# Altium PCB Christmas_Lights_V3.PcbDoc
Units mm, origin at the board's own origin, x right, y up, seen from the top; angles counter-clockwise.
Board outline 88.09 x 97.97 mm, 4 copper layers (Top Layer, Layer 1, Layer 2, Bottom Layer), stack 1.547 mm thick; 70 components, 43 nets, 269 pads, 454 vias.
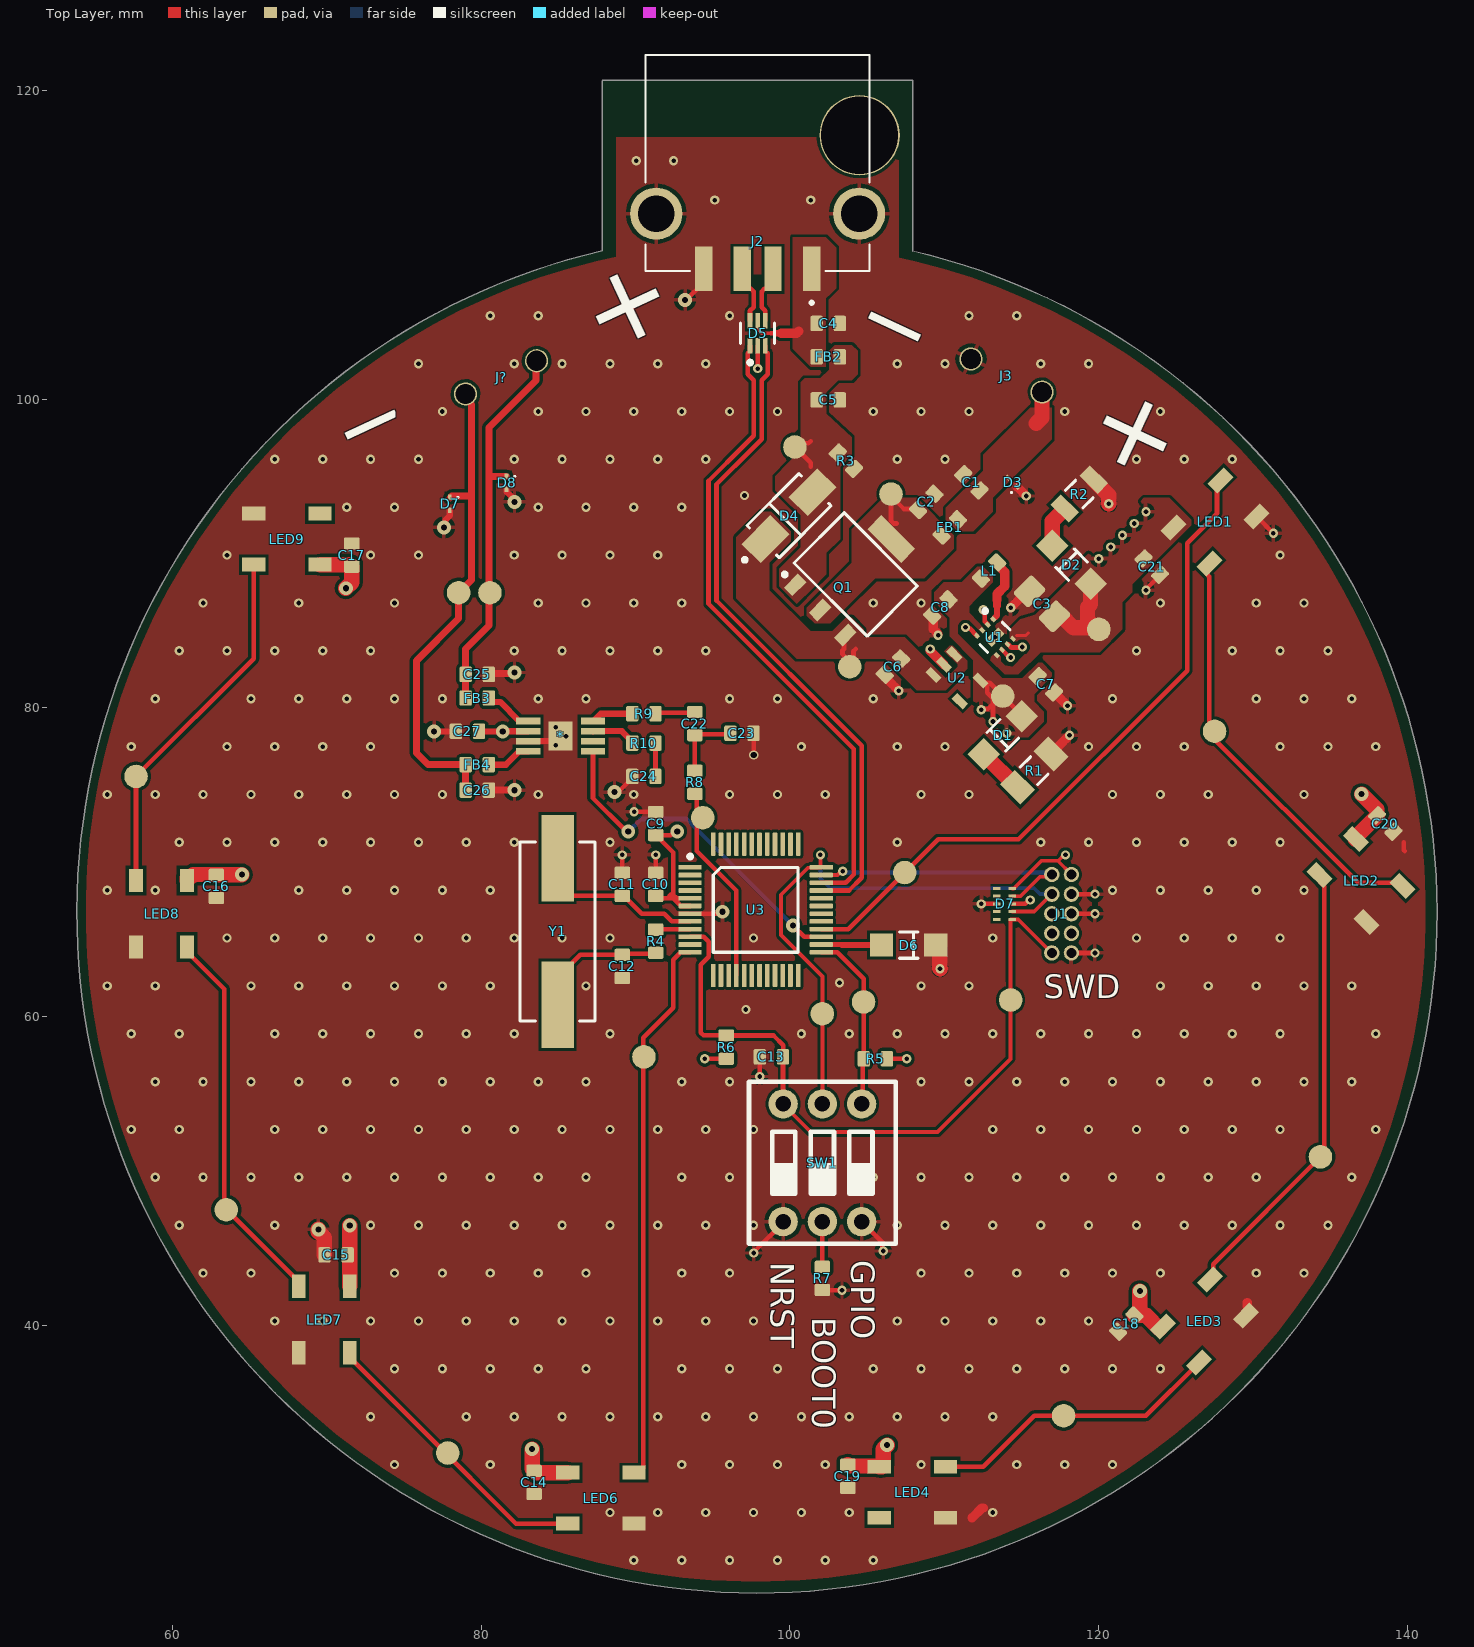
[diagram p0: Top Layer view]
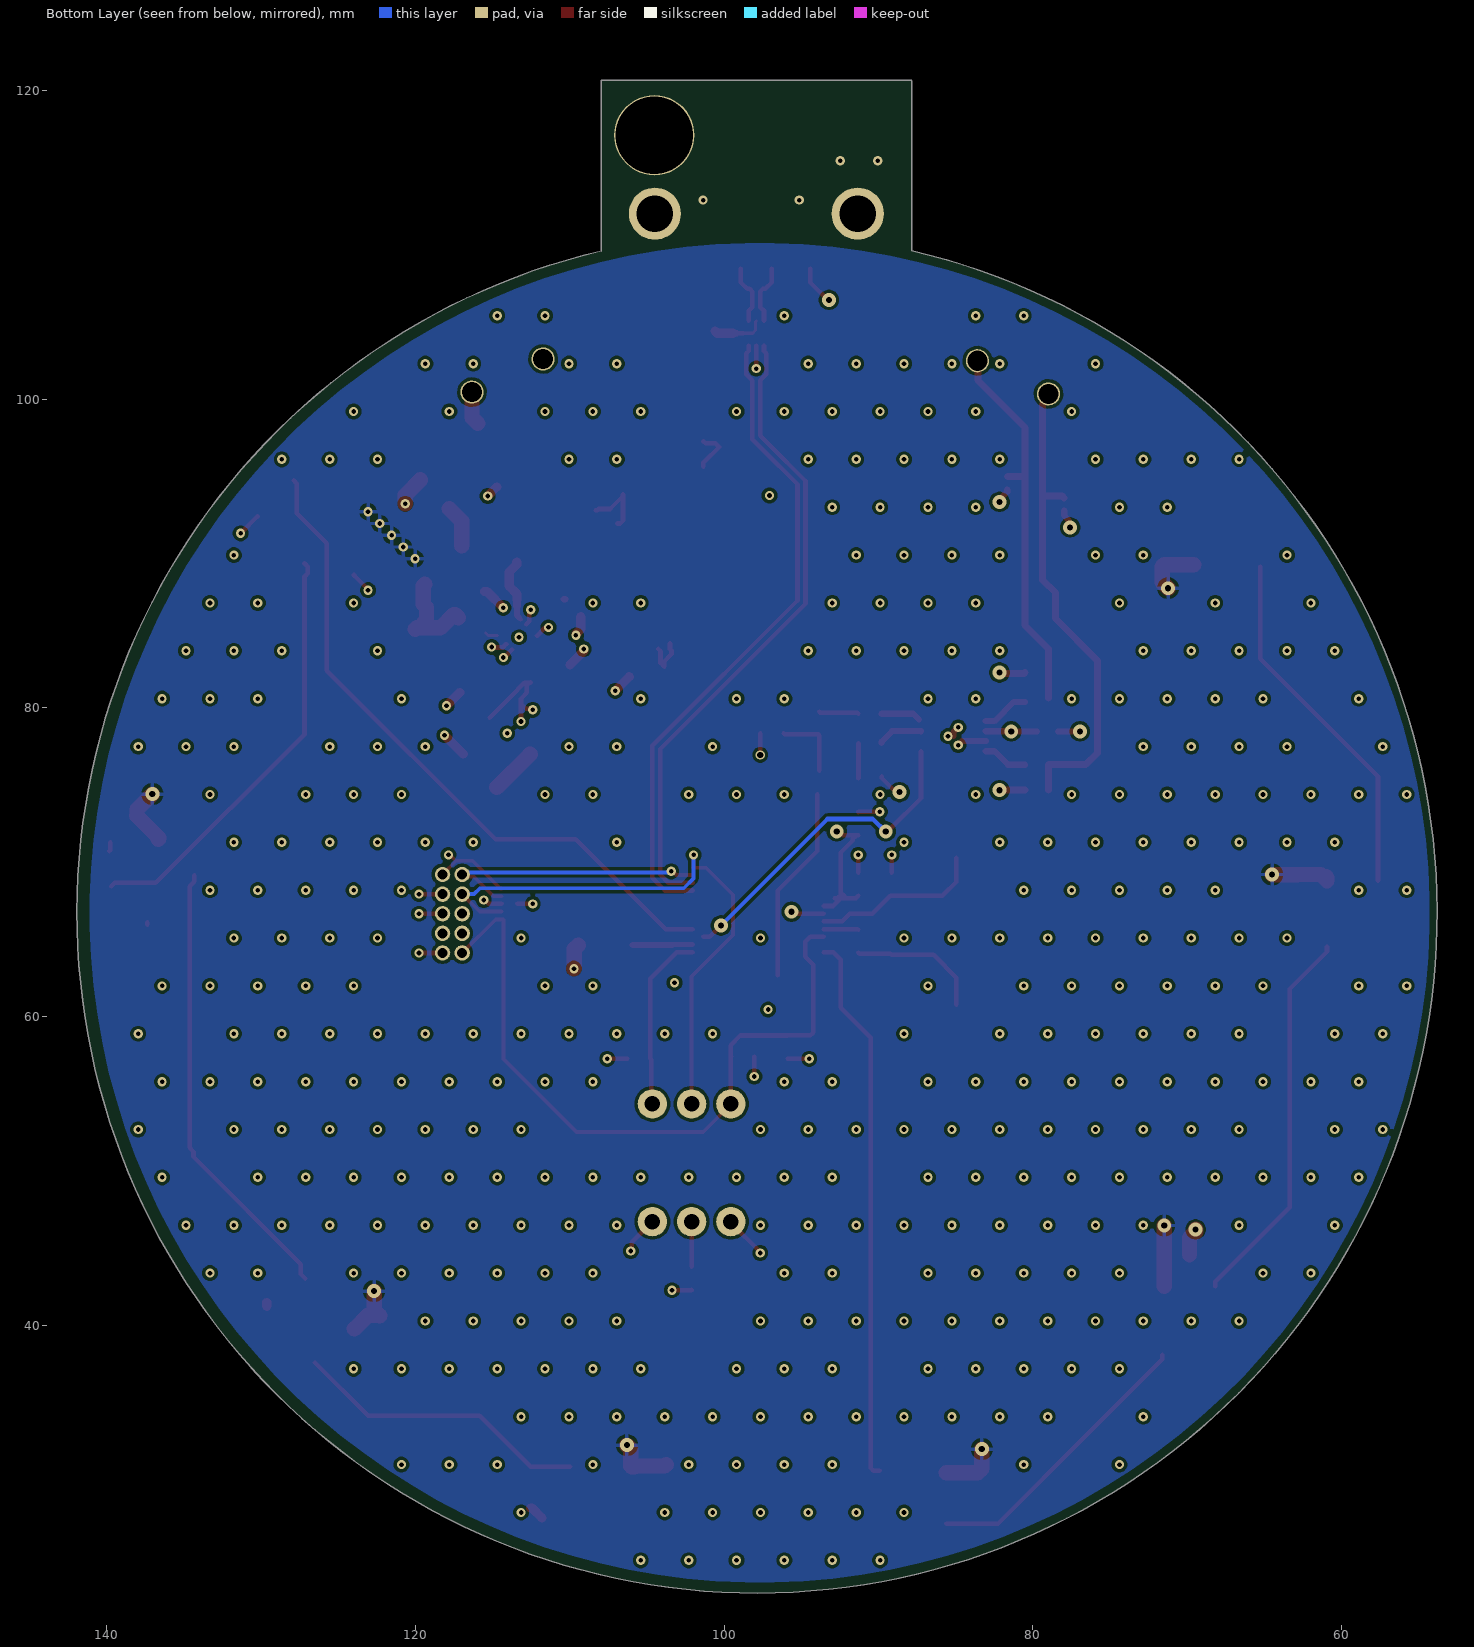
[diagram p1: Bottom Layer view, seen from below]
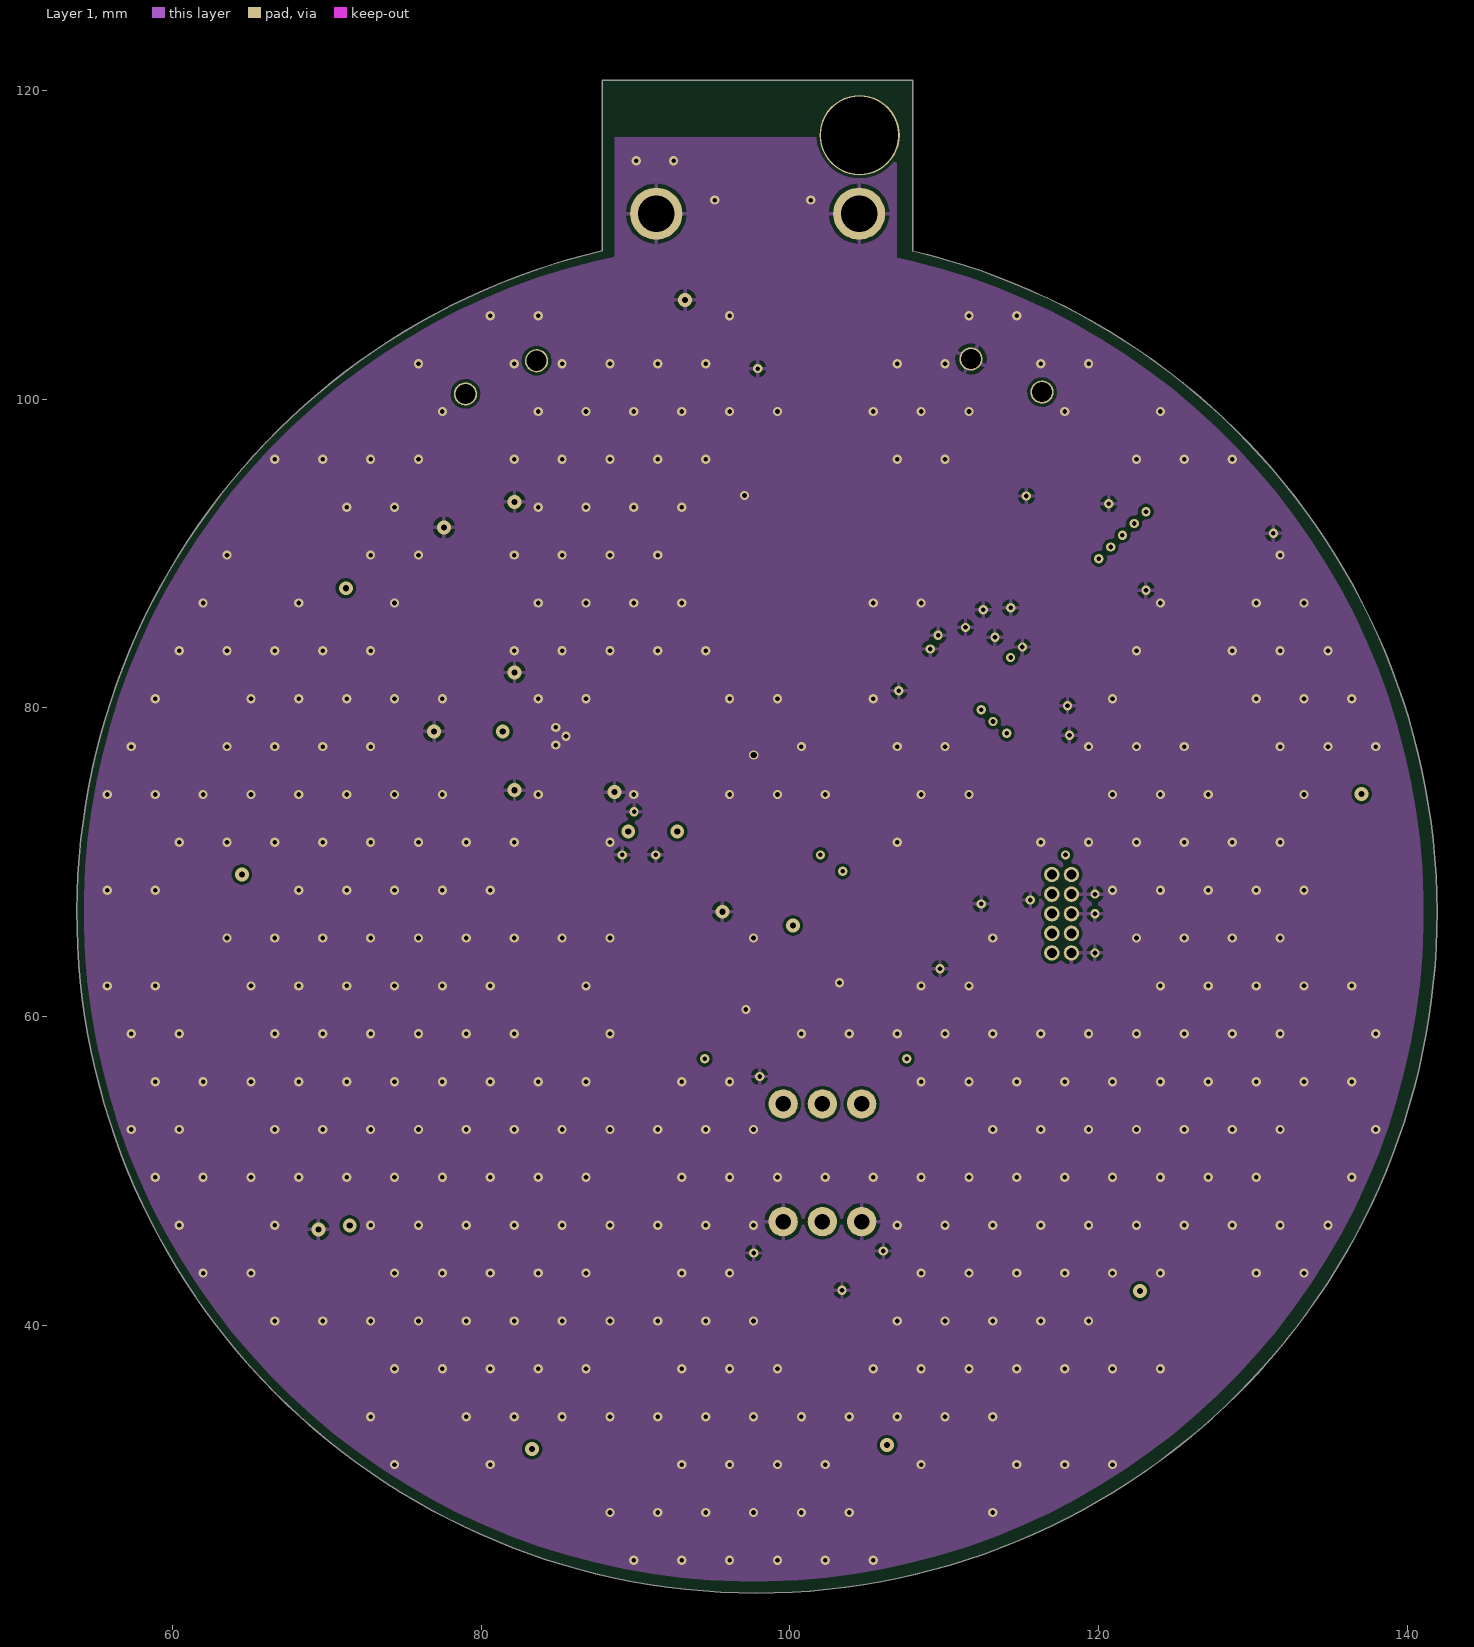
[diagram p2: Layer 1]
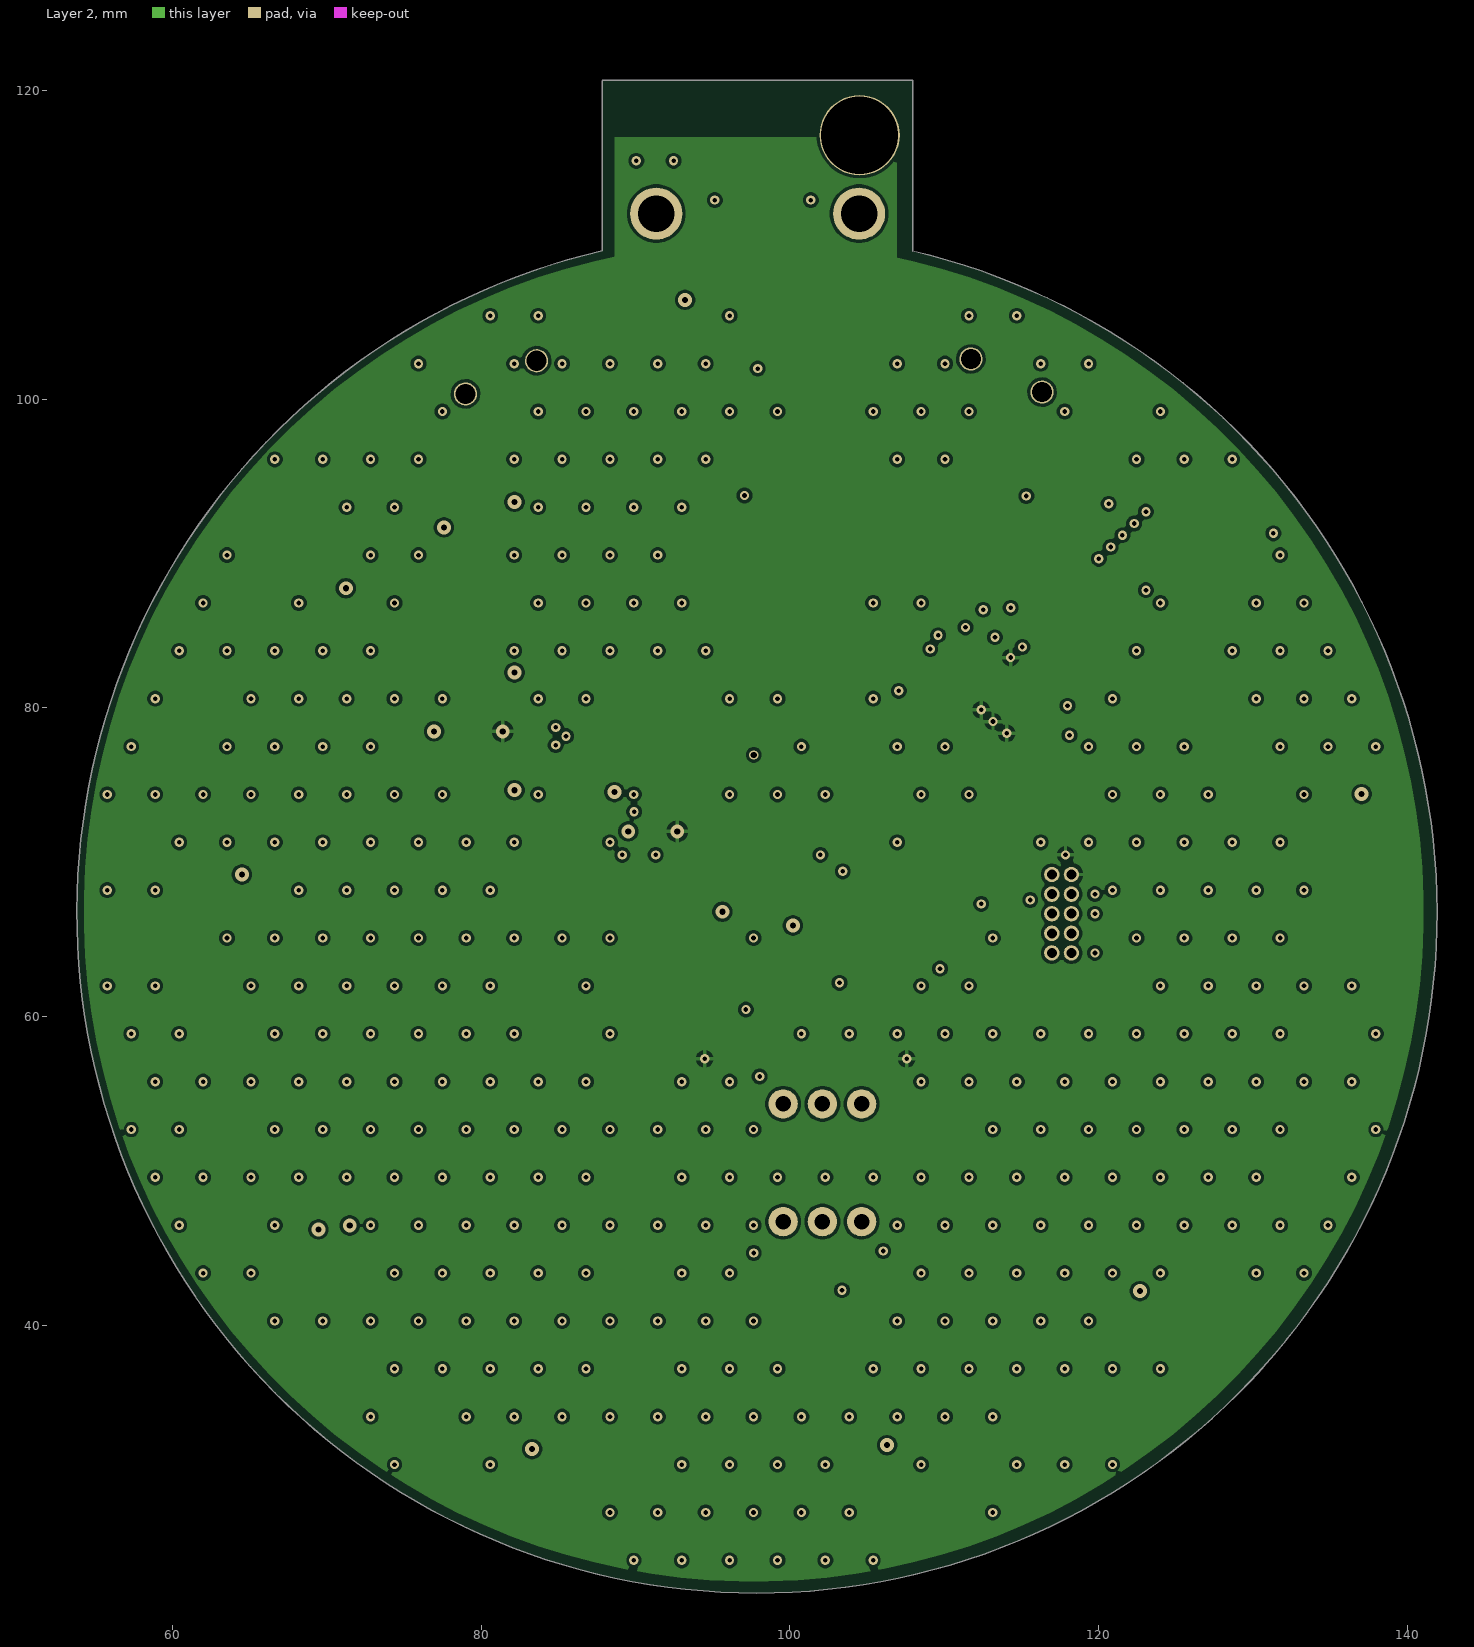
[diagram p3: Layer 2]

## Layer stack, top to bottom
Top Solder: solder mask 0.035, Solder Resist, Dk 3.5
Top Layer: signal copper 0.0152
Dielectric 2: prepreg 0.2104, PP-006, Dk 4.4
Layer 1: signal copper 0.0152
Dielectric 1: dielectric 1.065, FR-4, Dk 4.6
Layer 2: signal copper 0.0152
Dielectric 3: prepreg 0.2104, PP-006, Dk 4.4
Bottom Layer: signal copper 0.0152
Bottom Solder: solder mask 0.035, Solder Resist, Dk 3.5

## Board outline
87.844,109.608 ccw(c97.874,66.722) 107.963,109.594 107.975,109.606 107.975,120.65 87.884,120.65 87.844,120.61

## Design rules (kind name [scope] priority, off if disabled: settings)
Clearance Clearance_1 [All] p1: gap=0.2 ignorepadtopadclearanceinfootprint=FALSE except(0: Hole-Hole)
Clearance [All] p2: gap=0.254 ignorepadtopadclearanceinfootprint=FALSE ismatrix=TRUE
DiffPairsRouting DifferentialPairsRouting_1 [InDifferentialPairClass('All Differential Pairs')] p1: maxlimit=0.215 minlimit=0.127 mostfreqgap=0.215 toplayer_mingap=0.215 toplayer_minwidth=0.3 toplayer_maxwidth=0.3 toplayer_prefwidth=0.3 midlayer1_maxgap=0.127 midlayer1_prefgap=0.127 midlayer1_minwidth=0.13 midlayer1_maxwidth=0.13 midlayer1_prefwidth=0.13 midlayer2_maxgap=0.127 midlayer2_prefgap=0.127 midlayer2_minwidth=0.13 midlayer2_maxwidth=0.13 midlayer2_prefwidth=0.13 bottomlayer_mingap=0.215 bottomlayer_minwidth=0.3 bottomlayer_maxwidth=0.3 bottomlayer_prefwidth=0.3 impedanceprofiledriven=TRUE impedanceprofileid={5123043F-F303-4BC8-AD94-21C5BF75EB49} impedanceprofilevalue=90.000000 maxuncoupledlength=12.7
DiffPairsRouting [All] p2: maxlimit=0.254 minlimit=0.254 mostfreqgap=0.254 toplayer_minwidth=0.381 toplayer_maxwidth=0.381 toplayer_prefwidth=0.381 midlayer1_minwidth=0.381 midlayer1_maxwidth=0.381 midlayer1_prefwidth=0.381 midlayer2_minwidth=0.381 midlayer2_maxwidth=0.381 midlayer2_prefwidth=0.381 bottomlayer_minwidth=0.381 bottomlayer_maxwidth=0.381 bottomlayer_prefwidth=0.381 maxuncoupledlength=12.7
MinimumSolderMaskSliver [All] p1: minsoldermaskwidth=0.1
PlaneConnect [All] p1: pad.planeconnectstyle=Direct pad.reliefexpansion=0.508 pad.reliefentries=4 pad.reliefconductorwidth=0.254 pad.reliefairgap=0.254 via.planeconnectstyle=Relief via.reliefexpansion=0.508 via.reliefentries=4 via.reliefconductorwidth=0.254 via.reliefairgap=0.254
PolygonConnect [All] p1: thpad.connectstyle=Relief thpad.reliefconductorwidth=0.254 thpad.reliefentries=4 thpad.polygonreliefangle="90 Angle" thpad.airgapwidth=0.254 smdpad.connectstyle=Direct smdpad.reliefconductorwidth=0.254 smdpad.reliefentries=4 smdpad.polygonreliefangle="90 Angle" smdpad.airgapwidth=0.254 via.connectstyle=Relief via.reliefconductorwidth=0.254 via.reliefentries=4 via.polygonreliefangle="90 Angle" via.airgapwidth=0.254
RoutingVias RoutingViaStyle_1 [All] p1: holewidth=0.4 width=0.9 viastyle="Through Hole" minholewidth=0.3 minwidth=0.6 maxholewidth=1 maxwidth=1
RoutingVias [All] p2: holewidth=0.711 width=1.27 viastyle="Through Hole" minholewidth=0.711 minwidth=1.27 maxholewidth=0.711 maxwidth=1.27
SolderMaskExpansion [All] p1: expansion=0.102 istentingtop=FALSE
UnRoutedNet [All] p1: checkbadconnections=TRUE
Width [All] p1: maxlimit=1 minlimit=0.2 preferedwidth=0.3 midlayer1_maxwidth=0.254 midlayer1_prefwidth=0.254 midlayer2_maxwidth=0.254 midlayer2_prefwidth=0.254 minimp=50.000000 maximp=50.000000 favimp=50.000000
26 further rules are at their usual default settings.

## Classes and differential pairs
component class Christmas_Lights_V3: * C1 C3 C4 C5 C7 C8 C9 C11 C13 C14 C17 C19 C20 C21 C25 D4 D6 D7 FB1 FB3 J1 J? L1 LED1 LED2 LED3 LED8 LED9 Q1 R1 R2 R6 R8 R9 SW1 U2 U3 Y1

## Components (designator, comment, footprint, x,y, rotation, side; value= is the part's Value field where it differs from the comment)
* "TPA2005D1DGN" TPA2005D1DGN 87.249,77.201 r180 top
C1 "2u2" CAP_0603 111.76,94.615 r315 top
C2 "2u2" CAP_0603 108.839,93.345 r225 top
C3 "22u" CAP_0805 116.332,86.741 r315 top
C4 "2u2" CAP_0603 102.489,104.902 r180 top
C5 "2u2" CAP_0603 102.489,99.949 r180 top
C6 "1u" CAP_0603 106.68,82.677 r45 top
C7 "1u" CAP_0603 116.586,81.534 r135 top
C8 "4u7" CAP_0603 109.75,86.509 r45 top
C9 "2u2" CAP_0603 91.313,72.517 r270 top
C10 "100n" CAP_0603 91.313,68.58 r270 top
C11 "16p" CAP_0603 89.154,68.58 r270 top
C12 "16p" CAP_0603 89.154,63.258 r90 top
C13 "100n" CAP_0603 98.806,57.404 r0 top
C14 "100n" CAP_0603 83.439,29.845 r90 top
C15 "100n" CAP_0603 70.612,44.577 r0 top
C16 "100n" CAP_0603 62.865,68.441 r90 top
C17 "100n" CAP_0603 71.628,89.904 r270 top
C18 "100n" CAP_0603 121.793,40.132 r45 top
C19 "100n" CAP_0603 103.759,30.238 r90 top
C20 "100n" CAP_0603 138.557,72.517 r135 top
C21 "100n" CAP_0603 123.444,89.154 r135 top
C22 "3n3" CAP_0603 93.853,78.994 r270 top
C23 "3n3" CAP_0603 96.901,78.359 r0 top
C24 "3n3" CAP_0603 90.551,75.565 r0 top
C25 "1n" CAP_0603 79.756,82.178 r180 top
C26 "1n" CAP_0603 79.756,74.676 r180 top
C27 "1u" CAP_0603 79.121,78.486 r0 top
D1 "HSMG-C150" FP-HSMG-C150-MFG 113.792,78.232 r45 top
D2 "HSMG-C150" FP-HSMG-C150-MFG 118.237,89.281 r315 top
D3 "ESD9B5.0ST5G" ONSC-SOD-923-2-514AB-01_V 114.427,94.615 r135 top
D4 "SS14" FP-403AE-MFG 99.949,92.456 r225 top
D5 "USBLC6-2P6" FP-SOT-666-MFG 97.917,104.267 r90 top
D6 "HSMG-C150" FP-HSMG-C150-MFG 107.696,64.643 r180 top
D7 "ESD9B5.0ST5G" ONSC-SOD-923-2-514AB-01_V 77.978,93.218 r270 top
D7 "PUSB3AB4Z" SOT1176-1 114.411,66.31 r180 top
D8 "ESD9B5.0ST5G" ONSC-SOD-923-2-514AB-01_V 81.661,94.576 r270 top
FB1 "120R" FB_0603 110.363,91.694 r225 top
FB2 "120R" FB_0603 102.489,102.743 r0 top
FB3 "120R" FB_0603 79.756,80.645 r180 top
FB4 "120R" FB_0603 79.756,76.327 r180 top
J1 "10 pin header" "5x2 10 pin (1.27mm)" 116.967,69.215 r270 top
J2 "USBA 2.0" "USB A 87583 2010" 98.044,114.808 r180 top
J3 "2 pin header" "Screw connector" 116.332,100.457 r155 top
J? "2 pin header" "Screw connector" 83.598,102.485 r205 top
L1 "1u" IND_0603 112.903,88.9 r45 top
LED1 "COM-16347 WS2812B" COM-16347 124.841,91.694 r45 top
LED2 "COM-16347 WS2812B" COM-16347 136.652,71.501 r315 top
LED3 "COM-16347 WS2812B" COM-16347 124.166,39.933 r45 top
LED4 "COM-16347 WS2812B" COM-16347 105.791,30.859 r0 top
LED6 "COM-16347 WS2812B" COM-16347 85.616,30.478 r0 top
LED7 "COM-16347 WS2812B" COM-16347 71.499,42.545 r270 top
LED8 "COM-16347 WS2812B" COM-16347 60.958,68.816 r270 top
LED9 "COM-16347 WS2812B" COM-16347 69.578,89.283 r180 top
Q1 "BSP315P" INF-PG-SOT223_SC-73_L 104.267,88.646 r45 top
R1 "CRCW120682R0FKEA" FP-CRCW1206-e3-IPC_A 115.824,75.946 r225 top
R2 "CRCW1206180RFKEA" FP-CRCW1206-e3-IPC_C 118.745,93.853 r45 top
R3 "10k" RES_0603 103.632,96.012 r135 top
R4 "1k" RES_0603 91.313,64.897 r270 top
R5 "10k" RES_0603 105.537,57.277 r0 top
R6 "10k" RES_0603 95.885,58.039 r270 top
R7 "10k" RES_0603 102.108,43.053 r270 top
R8 "8.2k" RES_0603 93.853,75.184 r90 top
R9 "150k" RES_0603 90.551,79.629 r180 top
R10 "150k" RES_0603 90.551,77.724 r180 top
SW1 "DS01C-254-S-03BE" DS01C-254-S-03BE 102.108,50.546 r0 top locked
U1 "MIC2876-AYMT-T5" FP-TDFN22-8LD-PL-1-MFG 113.284,84.582 r315 top
U2 "XC6210B332MR-G" SOT25 110.654,83.476 r315 top
U3 "STM32C071 LQFP-48" LQFP-48 97.79,66.929 r0 top
Y1 "ABLS2-8.000MHZ-D4Y-T" FP-ABLS2-MFG 84.963,65.532 r270 top

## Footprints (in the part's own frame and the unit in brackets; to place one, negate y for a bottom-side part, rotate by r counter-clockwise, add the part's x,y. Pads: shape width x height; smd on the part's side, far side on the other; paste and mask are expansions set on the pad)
"5x2 10 pin (1.27mm)" [mm]
  round 1 hole 0.65 mask+0.05: 1(0,0) 2(0,1.27) 3(1.27,0) 4(1.27,1.27) 5(2.54,0) 6(2.54,1.27) 7(3.81,0) 8(3.81,1.27) 9(5.08,0) 10(5.08,1.27)
  body extent -0.64,-1.06 5.71,2.33, height 4
CAP_0603 [mm]
  rrect25% 0.8x1 smd: 1(-0.75,0) 2(0.75,0)
  body extent -0.8,-0.4 0.8,0.4, height 0.51
CAP_0805 [mm]
  rrect25% 1.4x1.7 smd: 1(-1.143,0) 2(1.143,0)
  body extent -1.15,-0.76 1.15,0.79, height 1.01
COM-16347 [mm]
  rect 1.5x0.9 smd: 1(0,0) 2(0,-3.3) 3(4.3,0) 4(4.3,-3.3)
  body extent -0.55,-4.15 4.86,0.85, height 1.6
DS01C-254-S-03BE [mm]
  round 1.9 hole 1: 1(-2.54,-3.81) 2(0,-3.81) 3(2.54,-3.81) 4(2.54,3.81) 5(0,3.81) 6(-2.54,3.81)
  silkscreen extent -4.75,-5.25 4.75,5.25, body extent -4.52,-4.95 4.52,4.95, height 6.56
FB_0603 [mm]
  rrect25% 0.8x1 smd: 1(-0.75,0) 2(0.75,0)
  body extent -0.8,-0.4 0.8,0.4, height 0.81
FP-403AE-MFG [mm]
  rect 2.65x1.75 smd paste+0 mask+0: 1(-2.15,0) 2(2.15,0)
  silkscreen extent -2.37,-1.48 4.17,1.48, body extent -3.57,-1.58 3.57,1.58, height 0.25
FP-ABLS2-MFG [mm]
  rect 5.6x2.1 smd paste+0 mask+0: 1(-4.75,0) 2(4.75,0)
  silkscreen extent -5.8,-2.42 5.8,2.42, body extent -7.65,-2.52 7.65,2.52, height 0.25
FP-CRCW1206-e3-IPC_A [mm]
  rect 1.356x1.858 smd paste+0 mask+0: 1(-1.526,0) 2(1.526,0)
  silkscreen extent -0.47,-0.8 0.47,0.8, body extent -2.7,-1.43 2.7,1.43, height 0.25
FP-CRCW1206-e3-IPC_C [mm]
  rect 0.956x1.658 smd paste+0 mask+0: 1(-1.326,0) 2(1.326,0)
  silkscreen extent -0.47,-0.8 0.47,0.8, body extent -1.9,-0.97 1.9,0.97, height 0.25
FP-HSMG-C150-MFG [mm]
  rect 1.5x1.5 smd paste+0 mask+0: 1(-1.75,0) 2(1.75,0)
  silkscreen extent -0.6,-0.85 0.6,0.85, body extent -2.6,-0.95 2.6,0.95, height 0.25
FP-SOT-666-MFG [mm]
  rect 0.99x0.3 smd paste+0 mask+0: 1(-0.805,0.5) 2(-0.805,0) 3(-0.805,-0.5) 4(0.805,-0.5) 5(0.805,0) 6(0.805,0.5)
  silkscreen extent -2.02,-1.1 0.65,1.1, body extent -1.4,-0.95 1.4,0.95, height 0.25
FP-TDFN22-8LD-PL-1-MFG [mm]
  rect 0.35x0.25 smd paste+0 mask+0: 1(-0.9,0.75) 2(-0.9,0.25) 3(-0.9,-0.25) 4(-0.9,-0.75) 5(0.9,-0.75) 6(0.9,-0.25) 7(0.9,0.25) 8(0.9,0.75)
  rect 0.6x1.2 smd paste-1000 mask+0: 9(0,0)
  silkscreen extent -1.77,-1.02 0.35,1.02, body extent -1.18,-1.13 1.18,1.13, height 0.25
IND_0603 [mm]
  rrect25% 0.8x1 smd: 1(-0.75,0) 2(0.75,0)
  body extent -0.81,-0.36 0.81,0.36, height 0.87
INF-PG-SOT223_SC-73_L [mm] "SOT223, 4-Leads, Body 6.5x3.5mm, Pitch 2.3mm, IPC High Density"
  rect 1.3x0.8 smd: 1(-3.25,2.3) 2(-3.25,0) 3(-3.25,-2.3)
  rect 1.3x3.1 smd: 4(3.25,0)
  silkscreen extent -3.37,-3.35 2.3,3.37, body extent -1.85,-3.35 1.85,3.35, height 1.8
LQFP-48 [mm]
  rrect25% 1.5x0.3 smd mask+0.05: 1(-4.25,2.75) 2(-4.25,2.25) 3(-4.25,1.75) 4(-4.25,1.25) 5(-4.25,0.75) 6(-4.25,0.25) 7(-4.25,-0.25) 8(-4.25,-0.75) 9(-4.25,-1.25) 10(-4.25,-1.75) 11(-4.25,-2.25) 12(-4.25,-2.75) 25(4.25,-2.75) 26(4.25,-2.25) 27(4.25,-1.75) 28(4.25,-1.25) 29(4.25,-0.75) 30(4.25,-0.25) 31(4.25,0.25) 32(4.25,0.75) 33(4.25,1.25) 34(4.25,1.75) 35(4.25,2.25) 36(4.25,2.75)
  rrect25% 0.3x1.5 smd mask+0.05: 13(-2.75,-4.25) 14(-2.25,-4.25) 15(-1.75,-4.25) 16(-1.25,-4.25) 17(-0.75,-4.25) 18(-0.25,-4.25) 19(0.25,-4.25) 20(0.75,-4.25) 21(1.25,-4.25) 22(1.75,-4.25) 23(2.25,-4.25) 24(2.75,-4.25) 37(2.75,4.25) 38(2.25,4.25) 39(1.75,4.25) 40(1.25,4.25) 41(0.75,4.25) 42(0.25,4.25) 43(-0.25,4.25) 44(-0.75,4.25) 45(-1.25,4.25) 46(-1.75,4.25) 47(-2.25,4.25) 48(-2.75,4.25)
  silkscreen extent -4.37,-2.75 2.75,3.57, body extent -4.5,-4.5 4.5,4.5, height 1.6
ONSC-SOD-923-2-514AB-01_V [mm] "SOD, 2-Leads, Body 0.8x0.6mm"
  rect 0.36x0.25 smd: 1(-0.42,0) 2(0.42,0)
  silkscreen extent -0.47,0.48 -0.37,0.57, body extent -0.4,-0.3 0.4,0.3, height 0.4
RES_0603 [mm]
  rrect25% 0.8x1 smd: 1(-0.75,0) 2(0.75,0)
  body extent -0.8,-0.43 0.8,0.43, height 0.52
"Screw connector" [mm]
  round 1.5 hole 1.3: 1(0,0) 2(5.08,0)
  body extent -3.09,-4.73 7.89,4.76, height 15.15
SOT25 [mm]
  rect 1x0.5 smd mask+0.05: 1(0,0) 2(0,-0.95) 3(0,-1.9) 4(2.4,-1.9) 5(2.4,0)
  body extent -0.2,-2.42 2.6,0.48, height 1.3
SOT1176-1 [mm]
  rect 0.475x0.2 smd mask+0.05: 1(0,0) 2(0,-0.5) 3(0,-1) 4(0,-1.5) 5(0,-2) 6(1,-2) 7(1,-1.5) 8(1,-1) 9(1,-0.5) 10(1,0)
  body extent 0,-2.25 1,0.25, height 0.5
TPA2005D1DGN [mil]
  rect 62x17 smd mask+1.97: 1(0,0) 2(0,-25.59) 3(0,-51.18) 4(0,-76.77) 5(165,-76.77) 6(165,-51.18) 7(165,-25.59) 8(165,0)
  rect 61.81x74.41 smd mask+1.97: 9(82.46,-38.39)
  body extent -14,-97 179,21, height 41
"USB A 87583 2010" [mm]
  rect 1.12x2.88 smd mask+0.05: 1(-3.373,6.374) 2(-0.873,6.374) 3(1.127,6.374) 4(3.627,6.374)
  round 3.376 hole 2.36 mask+0.05: 5(-6.443,2.794) 5(6.697,2.794)
  silkscreen extent -7.12,-7.49 7.38,8.66, body extent -7.12,-7.52 7.38,7.36, height 7.74

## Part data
C1 C2 C4 C5 C6 C7 C8 C9 C10 C11 C12 C13 C14 C15 C16 C17 C18 C19 C20 C21 C22 C23 C24 C25 C26 C27: library part CAP_0603, "Capacitor SMD 0603"
C3: library part CAP_0805, "Capacitor SMD 0805"
D1 D2 D6: library part CMP-2000-05061-2, "LED GREEN DIFFUSED 1206 SMD", Colour=Green, Forward Current=20mA, Forward Voltage=2.2V, Manufacturer=Broadcom, Max Junction Temp=+95°C, Power Dissipation=65mW, Reverse Voltage=5V, Temperature="-40°C to +85°C", Temperature Range High=+85°C, Temperature Range Low=-40°C
D3 D7 D8: library part CMP-1063-00119-1, "Transient Voltage Suppressor, Micro-Packaged Diode for ESD Protection, 2-Pin SOD-923, Pb-Free, Tape and Reel", Manufacturer="On Semiconductor"
D4: library part CMP-2000-04943-2, "DIODE SCHOTTKY 40V 1A SMA", Forward Current=1A, Manufacturer="ON Semiconductor", Max Junction Temp=+125°C, Max Repetitive Reverse Voltage=40V, Max Surge Forward Current=40A, Package=403AE, Peak Reverse Current=0.2mA, Temperature="-65°C to +125°C", Temperature Range Low=-65°C
D5: library part CMP-12225-000058-1, "TVS DIODE 5.25V 17V SOT666", Breakdown Voltage=6V, Capacitance=3.5pF, Case/Package=SOT-666, Clamping Voltage=17V, Leakage Current=150nA, Max Operating Temperature=125°C, Min Operating Temperature=-40°C, Operating Supply Voltage=5V, Package Quantity=1, Peak Pulse Current=5A, Power Line Protection=Yes, Test Current=1mA
FB1 FB2 FB3 FB4: library part FB_0603, "Ferrite Bead SMD 0603"
L1: library part IND_0603, "Inductor SMD 0603"
Q1: library part CMP-1099-00022-1, "P-Channel SIPMOS Small-Signal-Transistor, -60 V VDS, -1.17 A ID, -55 to 150 degC, PG-SOT223 (SC-73), Reel, Green", Manufacturer=Infineon
R1: library part CMP-2003-02405-2, "RES Thick Film, 82Ω, 1%, 0.25W, 100ppm/°C, 1206", Case Code (Imperial)=1206, Case Code (Metric)=3216, Max Operating Temperature=155°C, Max Power Dissipation=250mW, Min Operating Temperature=-55°C, Package Quantity=10, Resistance=82R, Temperature Coefficient=100ppm/°C, Tolerance=1%, Voltage Rating=200V
R2: library part CMP-2003-01848-2, "RES Thick Film, 180Ω, 1%, 0.25W, 100ppm/°C, 1206", Case Code (Imperial)=1206, Case Code (Metric)=3216, Max Operating Temperature=155°C, Min Operating Temperature=-55°C, Package Quantity=5000, Power Rating=250mW, Resistance=180R, Temperature Coefficient=100ppm/°C, Tolerance=1%, Voltage Rating=200V
R3 R4 R5 R6 R7 R8 R9 R10: library part RES_0603, "Resistor SMD 0603"
SW1: "DIP Switch SPST 3 Positions Short Pins 2.54mm Pitch", Manufacturer="CUI Devices"
U1: library part CMP-06325-000017-1, "IC REG BOOST ADJ 3.8A 8TDFN", Max Input Voltage=5.5V, Max Operating Temperature=125°C, Min Input Voltage=2.5V, Min Operating Temperature=-40°C, Output Current=3.8A, Switching Frequency=2MHz
Y1: library part CMP-27762-001729-1, "CRYSTAL 8.0000MHZ 18PF SMD", ESR (Equivalent Series Resistance)=80R, Frequency=8MHz, Frequency Stability=30ppm, Load Capacitance=18pF, Max Operating Temperature=85°C, Min Operating Temperature=-40°C, Operating Frequency="8 MHz", Package Quantity=1000

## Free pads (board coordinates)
  round 5.2 hole 5: 19(104.521,117.094)
  round 1.524 smd: 24(100.33,96.901) 25(57.658,75.565) 25(63.5,47.498) 25(77.851,31.75) 25(78.549,87.467) 25(80.581,87.467) 25(90.551,57.404) 25(94.361,72.898) 25(102.108,60.198) 25(103.886,82.677) 25(104.775,60.96) 25(106.553,93.853) 25(107.442,69.342) 25(113.792,80.772) 25(114.3,61.087) 25(117.729,34.163) 25(120.015,85.09) 25(127.508,78.486) 25(134.366,50.927)

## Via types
v1: diameter 0.6, hole 0.3, Top Layer to Bottom Layer, 433 vias
v2: diameter 0.9, hole 0.4, Top Layer to Bottom Layer, 20 vias
v3: diameter 0.6, hole 0.4, Top Layer to Bottom Layer, 1 vias

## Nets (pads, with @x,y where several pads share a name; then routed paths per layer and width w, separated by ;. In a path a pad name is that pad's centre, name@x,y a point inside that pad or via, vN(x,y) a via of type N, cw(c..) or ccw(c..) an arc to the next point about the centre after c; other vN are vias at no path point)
3V3: *.6 C7.2 C8.2 C9.2 C10.2 C27.2 D1.2 D7.5 J1.2 L1.1 pad.25@113.792,80.772 R5.2 R6.2 U1.3 U1.6 U2.5 U3.5 U3.6 | length 28.6
  Top Layer w0.25: D7.5 114.498,68.31 116.292,70.104 117.348,70.104 ; v1(117.856,70.485) 117.761,70.485 117.38,70.104 117.348,70.104 ; J1.2 117.348,70.104
  Top Layer w0.3: C10.2 91.464,67.679 92.202,67.679 92.202,67.691 ; C9.2 91.319,71.761 C9.2@91.419,71.761 ; 92.329,67.945 92.202,67.818 92.202,67.691 ; 92.401,67.945 92.667,67.679 U3.5@92.837,67.679 ; 92.44,67.945 92.44,70.64 91.663,71.417 91.663,71.517 C9.2@91.419,71.761 ; v2(92.71,72.009) 92.548,72.009 92.3,71.761 C9.2@91.419,71.761 ; U3.6 92.94,67.179 92.428,67.691 92.202,67.691 ; v1(94.488,57.277) 94.494,57.283 95.879,57.283 R6.2 ; R5.2 v1(107.569,57.277) ; v1(112.395,79.883) 112.452,79.94 112.833,79.94 113.157,80.264 ; U2.5@112.522,81.661 112.581,81.602 112.669,81.602 112.691,81.624 112.94,81.624 113.792,80.772 D1.2@115.189,79.375 ; 112.776,81.407 112.776,80.98 113.157,80.599 113.157,80.264 ; v1(113.157,79.121) 113.157,80.264 ; U1.6 114.247,83.265 v1(114.297,83.265)
  Top Layer w0.4: C27.2@79.756,78.486 v2(81.407,78.486) 81.414,78.493 83.05,78.493 *.6 ; C8.2 C8.2@110.39,87.04
  other v1: 114.046,78.359
+5: C3.2 C14.2 C15.2 C16.2 C17.2 C18.2 C19.2 C20.2 C21.2 D2.2 LED1.1 LED2.1 LED3.1 LED4.1 LED6.1 LED7.1 LED8.1 LED9.1 pad.25@120.015,85.09 U1.5 U1.8 | length 33.5
  Top Layer w0.2: 114.687,84.694 115.278,84.694 115.443,84.858
  Top Layer w1: LED8.1 60.958,69.016 61.008,69.066 61.208,69.066 61.357,69.215 C16.2@62.865,69.215 ; C16.2 64.492,69.191 v2(64.516,69.215) ; LED9.1 71.499,89.283 C17.2 71.628,88.138 v2(71.247,87.757) ; LED7.1 C15.2@71.499,44.831 ; C15.2@71.501,44.716 v2(71.501,46.482) ; v2(83.312,32.004) 83.312,30.722 C14.2 ; C14.2@83.568,30.478 LED6.1 ; C19.2 103.838,30.909 LED4.1@105.541,30.909 ; LED4.1 105.991,30.859 106.041,30.909 106.041,32 v2(106.299,32.258) ; C3.2@117.221,85.852 117.408,86.039 117.529,86.039 118.378,85.19 pad.25@119.773,85.19 ; D2.2@119.38,88.011 119.474,87.917 119.474,86.708 119.279,86.513 119.279,85.684 pad.25@119.773,85.19 ; pad.25@120.015,85.09 119.915,85.19 pad.25@119.773,85.19 ; C18.2@122.301,40.64 C18.2 ; v2(122.671,42.235) 122.671,41.01 C18.2 ; LED3.1@123.954,39.791 123.083,40.662 C18.2 ; LED2.1 136.624,71.529 136.624,71.6 C20.2@138.049,73.025 ; v2(137.033,74.422) 138.027,73.428 C20.2
  other v1: 120.015,89.662 120.777,90.424 121.539,91.186 122.301,91.948 123.063,92.71
Crystal_out: C12.2 R4.2 Y1.2 | length 8.8
  Top Layer w0.3: Y1.2 84.963,62.532 86.439,64.008 C12.2 89.223,64.077 91.244,64.077 R4.2
GND: *.7 *.9 C1.1 C2.1 C3.1 C4.1 C5.1 C6.1 C7.1 C8.1 C9.1 C10.1 C11.1 C12.1 C13.1 C14.1 C15.1 C16.1 C17.1 C18.1 C19.1 C20.1 C21.1 C23.2 C24.1 C25.1 C26.1 C27.1 D3.1 D5.2 D6.1 D7.2@77.978,92.798 D7.3 D7.8 D8.2 J1.4 J1.6 J1.10 J2.4 J2.5 J3.2 LED1.4 LED2.4 LED3.4 LED4.4 LED6.4 LED7.4 LED8.4 LED9.4 R1.1 R2.2 R3.1 R7.2 SW1.1 SW1.3 U1.2 U1.4 U1.7 U1.9 U2.2 U3.7 | length 60.3
  Top Layer w0.3: v2(88.646,74.549) 88.761,74.664 89,74.664 89.801,75.465 C24.1 ; C11.1 v1(89.154,70.485) ; v1(89.916,73.279) 89.922,73.273 91.307,73.273 C9.1 ; C10.1 v1(91.313,70.485) ; v2(93.218,106.426) 93.289,106.426 94.417,107.554 J2.4 ; U3.7 95.346,66.679 95.469,66.802 v2(95.631,66.802) ; C23.2 97.657,78.353 97.657,76.968 v3(97.663,76.962) ; v1(97.663,44.704) 97.663,44.767 99.568,46.672 SW1.1 ; v1(97.917,101.981) D5.2 ; v1(98.044,56.134) 98.05,56.14 98.05,57.398 C13.1 ; R7.2 102.114,42.297 103.372,42.297 v1(103.378,42.291) ; SW1.3 105.988,45.396 105.988,44.888 v1(106.045,44.831) ; C6.1@106.15,82.019 C6.1 ; v1@109.093,83.693 v1(109.093,83.82) ; C8.1 C8.1@109.291,85.908 ; v1(109.601,84.709) v1@109.601,84.79 ; v1(111.379,85.217) 111.436,85.16 111.646,85.16 U1.4 ; v1(112.395,67.31) D7.8 ; v1(112.522,86.36) 112.579,86.303 112.579,86.09 112.616,86.054 112.616,85.604 U1.2@112.807,85.413 ; U1.7 114.133,84.122 114.341,83.914 115.029,83.914 v1(115.062,83.947) ; D7.3 115.237,67.31 115.49,67.563 v1(115.571,67.563) ; J1.10 v1(119.761,64.135) ; J1.6 v1(119.761,66.675) ; J1.4 v1(119.761,67.945) ; v1(123.063,87.63) 123.063,87.671 123.974,88.582 C21.1 ; LED1.4 130.23,92.401 v1(131.318,91.313) ; LED2.4@137.359,65.968 LED2.4 ; 139.77,71.304 139.77,70.796 139.827,70.739
  Top Layer w0.4: v2(76.962,78.486) C27.1 ; v2(77.597,91.694) 77.693,91.79 77.693,92.171 77.978,92.456 D7.2@77.978,92.798 ; D8.2 81.661,93.988 82.169,93.48 v2(82.169,93.345) ; *.7 84.582,77.851 v1(84.836,77.597) ; v1(84.836,78.74) 85.155,78.421 *.9
  Top Layer w0.45: C26.1 v2(82.169,74.676) ; C25.1@80.506,82.296 80.565,82.237 82.11,82.237 v2(82.169,82.296)
  Top Layer w0.6: C6.1@106.15,82.019 v1(107.061,81.107) ; v1@109.093,83.693 U2.2 ; C8.1@109.291,85.908 109.291,85.1 v1@109.601,84.79 ; 111.806,27.559 112.441,28.194 112.522,28.194 ; v1(114.3,86.487) 115.362,87.549 C3.1 ; D3.1 v1(115.316,93.726) ; R1.1 v1(118.11,78.232) ; C7.1 v1(117.983,80.137) ; LED3.4@129.63,41.252 129.63,41.492
  Top Layer w1: v2(69.469,46.228) 69.469,46.093 69.862,45.7 C15.1 ; D6.1 109.696,64.393 109.696,63.151 v1(109.728,63.119) ; R2.2 119.683,94.76 120.65,93.792 v1(120.65,93.218)
  other v1: 89.9,24.8 93,24.8 96.1,24.8 99.2,24.8 102.3,24.8 105.4,24.8 88.35,27.9 91.45,27.9 94.55,27.9 97.65,27.9 100.75,27.9 103.85,27.9 113.15,27.9 74.4,31 80.6,31 93,31 96.1,31 99.2,31 102.3,31 108.5,31 114.7,31 117.8,31 120.9,31 72.85,34.1 79.05,34.1 82.15,34.1 85.25,34.1 88.35,34.1 91.45,34.1 94.55,34.1 97.65,34.1 100.75,34.1 103.85,34.1 106.95,34.1 110.05,34.1 113.15,34.1 74.4,37.2 77.5,37.2 80.6,37.2 83.7,37.2 86.8,37.2 93,37.2 96.1,37.2 99.2,37.2 105.4,37.2 108.5,37.2 111.6,37.2 114.7,37.2 117.8,37.2 120.9,37.2 124,37.2 66.65,40.3 69.75,40.3 72.85,40.3 75.95,40.3 79.05,40.3 82.15,40.3 85.25,40.3 88.35,40.3 91.45,40.3 94.55,40.3 97.65,40.3 106.95,40.3 110.05,40.3 113.15,40.3 116.25,40.3 119.35,40.3 62,43.4 65.1,43.4 74.4,43.4 77.5,43.4 80.6,43.4 83.7,43.4 86.8,43.4 93,43.4 96.1,43.4 108.5,43.4 111.6,43.4 114.7,43.4 117.8,43.4 120.9,43.4 124,43.4 130.2,43.4 133.3,43.4 60.45,46.5 66.65,46.5 72.85,46.5 75.95,46.5 79.05,46.5 82.15,46.5 85.25,46.5 88.35,46.5 91.45,46.5 94.55,46.5 97.65,46.5 106.95,46.5 110.05,46.5 113.15,46.5 116.25,46.5 119.35,46.5 122.45,46.5 125.55,46.5 128.65,46.5 131.75,46.5 134.85,46.5 58.9,49.6 62,49.6 65.1,49.6 68.2,49.6 71.3,49.6 74.4,49.6 77.5,49.6 80.6,49.6 83.7,49.6 86.8,49.6 93,49.6 96.1,49.6 99.2,49.6 102.3,49.6 105.4,49.6 108.5,49.6 111.6,49.6 114.7,49.6 117.8,49.6 120.9,49.6 124,49.6 127.1,49.6 130.2,49.6 136.4,49.6 57.35,52.7 60.45,52.7 66.65,52.7 69.75,52.7 72.85,52.7 75.95,52.7 79.05,52.7 82.15,52.7 85.25,52.7 88.35,52.7 91.45,52.7 94.55,52.7 97.65,52.7 113.15,52.7 116.25,52.7 119.35,52.7 122.45,52.7 125.55,52.7 128.65,52.7 131.75,52.7 137.95,52.7 58.9,55.8 62,55.8 65.1,55.8 68.2,55.8 71.3,55.8 74.4,55.8 77.5,55.8 80.6,55.8 83.7,55.8 86.8,55.8 93,55.8 96.1,55.8 108.5,55.8 111.6,55.8 114.7,55.8 117.8,55.8 120.9,55.8 124,55.8 127.1,55.8 130.2,55.8 133.3,55.8 136.4,55.8 57.35,58.9 60.45,58.9 66.65,58.9 69.75,58.9 72.85,58.9 75.95,58.9 79.05,58.9 82.15,58.9 88.35,58.9 100.75,58.9 103.85,58.9 106.95,58.9 110.05,58.9 113.15,58.9 116.25,58.9 119.35,58.9 122.45,58.9 125.55,58.9 128.65,58.9 131.75,58.9 137.95,58.9 97.156,60.469 55.8,62 58.9,62 65.1,62 68.2,62 71.3,62 74.4,62 77.5,62 80.6,62 86.8,62 108.5,62 111.6,62 124,62 127.1,62 130.2,62 133.3,62 136.4,62 103.215,62.202 63.55,65.1 66.65,65.1 69.75,65.1 72.85,65.1 75.95,65.1 79.05,65.1 82.15,65.1 85.25,65.1 88.35,65.1 97.65,65.1 113.15,65.1 122.45,65.1 125.55,65.1 128.65,65.1 131.75,65.1 55.8,68.2 58.9,68.2 68.2,68.2 71.3,68.2 74.4,68.2 77.5,68.2 80.6,68.2 120.9,68.2 124,68.2 127.1,68.2 130.2,68.2 133.3,68.2 60.45,71.3 63.55,71.3 66.65,71.3 69.75,71.3 72.85,71.3 75.95,71.3 79.05,71.3 82.15,71.3 88.35,71.3 106.95,71.3 116.25,71.3 119.35,71.3 122.45,71.3 125.55,71.3 128.65,71.3 131.75,71.3 55.8,74.4 58.9,74.4 62,74.4 65.1,74.4 68.2,74.4 71.3,74.4 74.4,74.4 77.5,74.4 83.7,74.4 89.9,74.4 96.1,74.4 99.2,74.4 102.3,74.4 108.5,74.4 111.6,74.4 120.9,74.4 124,74.4 127.1,74.4 133.3,74.4 57.35,77.5 63.55,77.5 66.65,77.5 69.75,77.5 72.85,77.5 100.75,77.5 106.95,77.5 110.05,77.5 119.35,77.5 122.45,77.5 125.55,77.5 131.75,77.5 134.85,77.5 137.95,77.5 85.508,78.173 58.9,80.6 65.1,80.6 68.2,80.6 71.3,80.6 74.4,80.6 77.5,80.6 83.7,80.6 86.8,80.6 96.1,80.6 99.2,80.6 105.4,80.6 120.9,80.6 130.2,80.6 133.3,80.6 136.4,80.6 60.45,83.7 63.55,83.7 66.65,83.7 69.75,83.7 72.85,83.7 82.15,83.7 85.25,83.7 88.35,83.7 91.45,83.7 94.55,83.7 122.45,83.7 128.65,83.7 131.75,83.7 134.85,83.7 113.284,84.582 62,86.8 68.2,86.8 74.4,86.8 83.7,86.8 86.8,86.8 89.9,86.8 93,86.8 105.4,86.8 108.5,86.8 124,86.8 130.2,86.8 133.3,86.8 63.55,89.9 72.85,89.9 75.95,89.9 82.15,89.9 85.25,89.9 88.35,89.9 91.45,89.9 131.75,89.9 71.3,93 74.4,93 83.7,93 86.8,93 89.9,93 93,93 97.064,93.762 66.65,96.1 69.75,96.1 72.85,96.1 75.95,96.1 82.15,96.1 85.25,96.1 88.35,96.1 91.45,96.1 94.55,96.1 106.95,96.1 110.05,96.1 122.45,96.1 125.55,96.1 128.65,96.1 77.5,99.2 83.7,99.2 86.8,99.2 89.9,99.2 93,99.2 96.1,99.2 99.2,99.2 105.4,99.2 108.5,99.2 111.6,99.2 117.8,99.2 124,99.2 75.95,102.3 82.15,102.3 85.25,102.3 88.35,102.3 91.45,102.3 94.55,102.3 106.95,102.3 110.05,102.3 116.25,102.3 119.35,102.3 80.6,105.4 83.7,105.4 96.1,105.4 111.6,105.4 114.7,105.4 95.14,112.893 101.363,112.893 90.06,115.433 92.473,115.433
IN+: *.3 R10.2 | length 2.9
  Top Layer w0.4: *.3@87.249,78.486 87.264,78.501 89.124,78.501 89.801,77.824 R10.2
IN-: *.4 R9.2 | length 2.6
  Top Layer w0.4: *.4@87.376,79.248 87.757,79.629 R9.2
LED1_IN: LED1.3 pad.25@107.442,69.342 U3.28 | length 43.8
  Top Layer w0.3: U3.28 103.779,65.679 109.601,71.501 114.808,71.501 125.73,82.423 125.73,90.678 127.669,92.617 127.669,94.522 LED1.3
"LED2 IN": LED6.3 pad.25@90.551,57.404 U3.12 | length 35.7
  Top Layer w0.3: LED6.3@89.916,30.607 90.345,30.607 90.516,30.778 90.516,58.639 92.456,60.579 92.456,63.695 92.94,64.179 U3.12
NetC22_1: C22.1 R9.1 | length 2.6
  Top Layer w0.3: R9.1@91.313,79.629 91.37,79.686 93.795,79.686 C22.1
NetC22_2: C22.2 C23.1 R8.2 | length 4.6
  Top Layer w0.3: R8.2 C22.2@93.853,78.232 ; C22.2 93.911,78.301 96.081,78.301 C23.1@96.139,78.359
NetC24_2: C24.2 R10.1 | length 2.3
  Top Layer w0.3: R10.1 C24.2 91.301,75.45 C24.2@91.313,75.438
NetD1_1: D1.1 R1.2 | length 3.1
  Top Layer w1: D1.1 112.586,76.995 114.714,74.867 R1.2
NetD2_1: D2.1 R2.1 | length 2.7
  Top Layer w1: D2.1 117,92.108 R2.1
NetD6_2: D6.2 U3.26 | length 3.9
  Top Layer w0.3: U3.26 103.342,64.679 103.378,64.643
  Top Layer w0.4: 103.378,64.643 D6.2
NetL1_2: L1.2 U1.1 | length 4.2
  Top Layer w0.3: U1.1 113.281,85.852 113.284,85.852
  Top Layer w0.4: 113.284,85.852 113.411,85.979 113.411,86.614
  Top Layer w0.5: 113.411,86.614 113.411,86.995
  Top Layer w0.6: 113.411,86.995 113.411,87.376 113.919,87.884 113.919,88.803 113.433,89.289 L1.2
NetLED1_2: LED1.2 LED2.3 pad.25@127.508,78.486 | length 27.8
  Top Layer w0.3: LED1.2 126.962,89.148 126.962,88.724 127.174,88.512 127.174,78.312 136.813,68.673 139.48,68.673 LED2.3
NetLED2_2: LED2.2 LED3.3 pad.25@134.366,50.927 | length 29.3
  Top Layer w0.3: LED3.3@127.127,43.053 127.419,43.345 127.419,43.98 134.366,50.927 134.366,51.258 134.62,51.512 134.62,68.442 134.319,68.743 LED2.2
NetLED3_2: LED3.2 LED4.3 pad.25@117.729,34.163 | length 19.2
  Top Layer w0.3: LED4.3@109.982,30.861 112.522,30.861 115.824,34.163 pad.25@117.729,34.163 ; pad.25@117.856,34.163 123.063,34.163 LED3.2
NetLED6_2: LED6.2 LED7.3 pad.25@77.851,31.75 | length 18.7
  Top Layer w0.3: LED7.3@71.628,38.1 71.628,37.816 77.773,31.672 80.899,28.545 82.266,27.178 LED6.2
NetLED7_2: LED7.2 LED8.3 pad.25@63.5,47.498 | length 25
  Top Layer w0.3: LED8.3@60.96,64.516 60.96,64.214 63.373,61.801 63.373,47.671 68.199,42.845 LED7.2
NetLED8_2: LED8.2 LED9.3 pad.25@57.658,75.565 | length 23.5
  Top Layer w0.3: LED8.2 57.658,75.565 65.278,83.185 LED9.3@65.278,89.154
NetR5_1: pad.25@104.775,60.96 R5.1 SW1.4 U3.25 | length 11.6
  Top Layer w0.3: U3.25 103.08,64.179 104.787,62.472 R5.1 104.717,57.207 104.717,54.425 SW1.4
NetR7_1: R7.1 SW1.2 | length 2.9
  Top Layer w0.3: R7.1 SW1.2
NRST: C13.2 D7.1@114.411,66.31 J1.9 pad.25@114.3,61.087 R6.1 SW1.6 U3.10 | length 47
  Top Layer w0.25: SW1.6 99.568,54.336 101.358,52.546 109.569,52.546 114.299,57.276 pad.25@114.299,61.087 ; 114.299,62.23 114.299,66.285 114.324,66.31 114.792,66.31 J1.9 ; pad.25@114.3,61.087 114.3,62.23
  Top Layer w0.3: U3.10 94.206,65.179 94.413,65.179 94.742,64.85 94.742,63.881 94.234,63.373 94.234,58.977 94.41,58.801 95.873,58.801 R6.1 98.945,58.789 99.568,58.166 99.568,57.416 C13.2 99.562,57.398 99.562,54.362 SW1.6
OSC_IN: C11.2 U3.8 Y1.1 | length 11.2
  Top Layer w0.3: Y1.1 84.963,68.73 85.863,67.83 C11.2 89.254,67.83 90.409,66.675 91.86,66.675 92.356,66.179 U3.8
OSC_OUT: R4.1 U3.9 | length 2.2
  Top Layer w0.3: R4.1 91.345,65.679 U3.9
Speaker_NSD: *.1 U3.27 | length 21.5
  Top Layer w0.3: *.1 87.249,74.168 89.281,72.136 89.408,72.136 v2(89.535,72.009) ; v2(100.203,65.913) 100.937,65.179 U3.27@101.346,65.179
  Bottom Layer w0.3: v2(89.535,72.009) 89.565,72.009 90.365,72.809 93.307,72.809 v2(100.203,65.913)
Speaker_out+: C25.2 D8.1 FB3.2 J?.1 pad.25@80.581,87.467 | length 24.7
  Top Layer w0.45: FB3.2 C25.2@79.006,82.03 ; C25.2 79.006,83.832 80.518,85.344 80.518,94.996 ; D8.1 80.518,94.996 ; J?.1@83.566,102.489 83.566,101.219 80.518,98.171 80.518,94.996
Speaker_out-: C26.2 D7.1@77.978,93.638 FB4.2 J?.2 pad.25@78.549,87.467 | length 31.5
  Top Layer w0.45: D7.1@77.978,93.599 78.105,93.726 79.375,93.726 ; J?.2@78.867,100.33 78.867,100.173 79.375,99.665 79.375,93.726 ; C26.2@78.994,74.676 79.006,74.688 FB4.2 76.581,76.327 75.819,77.089 75.819,83.058 78.549,85.788 78.549,87.467 79.375,88.293 79.375,93.726
Speaker_PWM: pad.25@94.361,72.898 R8.1 U3.16 | length 12.8
  Top Layer w0.3: R8.1@93.98,74.422 93.98,70.739 96.54,68.179 U3.16
Speaker_VO+: *.5 FB3.1 | length 3.1
  Top Layer w0.4: FB3.1@80.518,80.391 81.246,80.391 82.486,79.151 *.5
Speaker_VO-: *.8 FB4.1 | length 2.9
  Top Layer w0.4: FB4.1@80.518,76.327 81.613,76.327 82.486,77.201 *.8
SWCLK/BOOT0: D7.2@114.411,66.81 J1.3 pad.25@102.108,60.198 SW1.5 U3.36 | length 38.8
  Top Layer w0.25: v1(101.981,70.485) 101.981,69.688 102.015,69.654 101.177,69.654 99.428,67.905 99.428,65.291 102.108,62.611 102.108,60.198 SW1.5 ; D7.2@114.411,66.81 115.832,66.81 J1.3
  Bottom Layer w0.25: v1(101.981,70.485) 101.981,68.961 102.616,68.326 115.824,68.326 116.205,67.945 J1.3
SWDIO: D7.4 J1.1 U3.35 | length 18.3
  Top Layer w0.25: U3.35 103.09,69.179 103.332,69.421 v1(103.426,69.421) ; D7.4 114.934,67.81 116.196,69.071 116.823,69.071 J1.1
  Bottom Layer w0.25: v1(103.426,69.421) 103.493,69.354 116.828,69.354 J1.1
"USB_conn D_N": D5.6 J2.3 | length 3.9
  Top Layer w0.3: J2.3 96.917,107.554 97.327,107.144 97.484,107.144 97.659,106.968 97.659,105.954 97.417,105.712 D5.6
"USB_conn D_P": D5.4 J2.2 | length 3.9
  Top Layer w0.3: D5.4 98.417,105.712 98.175,105.954 98.175,106.968 98.35,107.144 98.507,107.144 98.917,107.554 J2.2
USB_D_N: D5.3 U3.33 | length 42.7
  Top Layer w0.3: D5.3 98.417,103.117 98.567,102.967 98.567,101.615 98.178,101.226 98.178,97.416 97.56,96.798 95.25,94.488 95.25,86.962 104.655,77.556 104.655,69.002 103.833,68.179 U3.33
USB_D_P: D5.1 U3.34 | length 41.9
  Top Layer w0.3: D5.1 97.417,103.117 97.267,102.967 97.267,101.615 97.663,101.219 97.663,97.63 97.045,97.011 94.735,94.701 94.735,86.748 104.14,77.343 104.14,69.215 103.619,68.694 103.604,68.694 ; U3.34 103.589,68.679
VBATT: C1.2 D3.2 FB1.1 J3.1 | length 2.2
  Top Layer w1: 115.951,98.425 116.332,98.806 J3.1
VBATT_Filt: C2.2 FB1.2 pad.25@106.553,93.853 Q1.2 Q1.4 | length 4.3
  Top Layer w0.3: pad.25@106.553,93.853 pad.25@106.553,93.726 ; 106.934,91.948 106.729,91.948 106.553,92.124 pad.25@106.553,93.726 ; C2.2 108.226,92.815 108.156,92.885 107.394,92.885 pad.25@106.553,93.726
VBUS: C4.2 D5.5 FB2.1 J2.1 | length 3.4
  Top Layer w0.2: D5.5 97.967,105.022 97.967,104.453 98.153,104.267 98.767,104.267
  Top Layer w0.3: 98.767,104.267 99.187,104.267
  Top Layer w0.4: 99.187,104.267 99.441,104.267
  Top Layer w0.6: 99.441,104.267 100.457,104.267 100.584,104.394
VBUS_Filt: C5.2 D4.1 FB2.2 pad.24 Q1.1 R3.2 | length 2.9
  Top Layer w0.3: 101.346,95.631 101.346,95.885 pad.24 100.564,97.135 101.199,97.135 101.346,97.282
VIN: C6.2 D4.2 pad.25@103.886,82.677 Q1.3 U2.1 U2.3 | length 3.1
  Top Layer w0.3: Q1.3@103.505,84.201 103.505,83.82 103.414,83.729 103.414,83.48 103.886,83.008 103.886,82.677 104.12,82.911 104.12,83.673 104.267,83.82
pads on no net: *.2 D7.6 D7.7 D7.9 D7.10 J1.5 J1.7 J1.8 LED4.2 LED9.2 U2.4 U3.1 U3.2 U3.3 U3.4 U3.11 U3.13 U3.14 U3.15 U3.17 U3.18 U3.19 U3.20 U3.21 U3.22 U3.23 U3.24 U3.29 U3.30 U3.31 U3.32 U3.37 U3.38 U3.39 U3.40 U3.41 U3.42 U3.43 U3.44 U3.45 U3.46 U3.47 U3.48

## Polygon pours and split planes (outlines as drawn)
GND on Top Layer "GND_L01_P029" (solid, pour order 29): 54.419,66.802 ccw(c97.79,66.802) 97.79,23.431 ccw(c97.79,66.802) 141.161,66.802 ccw(c97.79,66.802) 97.79,110.173 ccw(c97.79,66.802)
VBUS on Top Layer "VBUS_L01_P000" (solid, pour order 0): 102.324,110.49 100.203,110.49 100.203,106.172 100.203,103.251 101.366,102.088 102.324,102.088
VBUS on Top Layer "VBUS_L01_P001" (solid, pour order 1): 100.203,106.172 101.981,106.172 102.997,107.188 102.997,109.817 102.324,110.49 100.203,110.49
VBUS_Filt on Top Layer "VBUS_FILT_L01_P002" (solid, pour order 2): 102.903,103.505 104.013,103.505 104.394,103.124 104.394,101.6 104.013,101.219 103.124,101.219 102.362,100.457 102.362,99.06 100.711,99.06 100.711,101.092 100.965,101.346 101.981,101.346 102.545,101.91 102.545,103.147
VBUS_Filt on Top Layer "VBUS_FILT_L01_P004" (solid, pour order 4): 100.71,99.441 100.718,96.724 99.06,94.996 99.06,94.107 101.219,91.948 102.108,91.948 103.251,93.091 103.251,95.631 104.013,96.393 104.013,97.536 101.949,99.441
VBUS_Filt on Top Layer "VBUS_FILT_L01_P005" (solid, pour order 5): 100.711,93.44 100.711,90.424 99.314,89.027 99.314,87.884 100.203,86.995 100.457,86.741 101.473,87.757 102.362,88.646 102.362,90.043 103.251,90.932 103.251,94.075
VIN on Top Layer "VIN_L01_P007" (solid, pour order 7): 98.806,92.71 100.076,91.44 100.076,90.805 98.679,89.408 98.679,87.63 101.346,84.963 102.743,84.963 103.632,85.852 104.013,85.852 104.775,85.09 104.775,84.582 103.378,83.185 100.457,83.185 96.52,87.122 96.52,91.059 98.171,92.71
VBATT on Top Layer "VBATT_L01_P008" (solid, pour order 8): 115.57,99.441 116.967,99.441 116.967,97.409 113.157,93.599 113.157,92.71 111.887,91.44 110.871,91.44 110.109,92.202 110.109,92.964 112.522,95.377 112.522,96.393
VBATT_Filt on Top Layer "VBATT_FILT_L01_P009" (solid, pour order 9): 110.617,91.186 108.204,93.599 106.045,93.599 104.013,91.567 104.013,89.408 101.092,86.487 101.092,85.979 101.6,85.471 102.616,85.471 105.537,88.392 108.712,88.392 110.617,90.297
VIN on Top Layer "VIN_L01_P010" (solid, pour order 10): 102.108,83.185 106.172,83.185 108.204,81.153 110.109,81.153 111.506,82.55 111.506,83.058 110.446,84.118 110.011,83.683 110.871,82.823 110.871,82.677 110.109,81.915 109.22,82.804 107.442,84.582 103.505,84.582
+5 on Top Layer "+5_L01_P013" (solid, pour order 13): 113.345,83.618 113.651,83.312 113.665,83.312 113.665,83.019 113.908,82.776 114.427,82.677 115.311,83.561 115.311,84.455 115.443,85.606 115.824,85.979 119.126,89.281 120.015,89.281 121.539,87.757 121.539,85.09 120.067,83.618 116.257,83.618 114.808,82.169 113.919,82.169 112.984,83.104 113.039,83.312 113.289,83.561
+5 on Top Layer "+5_L01_P015" (solid, pour order 15): 116.807,86.321 114.928,85.732 114.256,85.059 114.245,84.51 114.554,84.328 115.189,84.328 115.884,83.761
3V3 on Top Layer "3V3_L01_P016" (solid, pour order 16): 111.887,82.169 111.887,79.756 114.203,77.44 114.867,78.105 115.443,78.105 116.459,79.121 116.459,79.756 115.824,80.391 115.824,80.899 116.967,82.042 116.967,82.296 116.332,82.931 116.078,82.931 115.062,81.915 113.773,81.915 110.871,84.817 110.871,85.217 111.252,85.598 111.715,85.598 112.5,84.814 112.649,84.963 112.649,85.126 112.05,85.725 111.542,86.233 111.125,86.233 110.363,85.471 110.363,84.63 111.887,83.106 111.887,83.058
3V3 on Top Layer "3V3_L01_P017" (solid, pour order 17): 111.935,85.84 111.633,86.142 111.633,86.995 110.49,88.138 109.982,88.138 109.347,87.503 109.347,86.868 110.363,85.852 110.363,85.283
3V3 on Top Layer "3V3_L01_P018" (solid, pour order 18): 109.982,88.138 111.125,88.138 112.141,89.154 112.522,89.154 113.157,88.519 113.157,88.138 112.014,86.995 111.61,86.591
+5 on Top Layer "+5_L01_P019" (solid, pour order 19): 118.933,84.262 122.174,87.503 122.174,88.011 125.984,91.821 125.984,92.202 124.587,93.599 122.936,93.599 118.933,89.596
GND on Top Layer "GND_L01_P030" (solid, pour order 30): 107.061,108.077 107.061,116.967 88.773,116.967 88.773,108.077
GND on Layer 1 "GND_L02_P023" (solid, pour order 23): 54.292,66.802 ccw(c97.663,66.802) 97.663,23.431 ccw(c97.663,66.802) 141.034,66.802 ccw(c97.663,66.802) 97.663,110.173 ccw(c97.663,66.802)
GND on Layer 1 "GND_L02_P024" (solid, pour order 24): 106.934,108.077 106.934,116.967 88.646,116.967 88.646,108.077
3V3 on Layer 2 "3V3_L03_P025" (solid, pour order 25): 54.292,66.802 ccw(c97.663,66.802) 97.663,23.431 ccw(c97.663,66.802) 141.034,66.802 ccw(c97.663,66.802) 97.663,110.173 ccw(c97.663,66.802)
3V3 on Layer 2 "3V3_L03_P026" (solid, pour order 26): 106.934,108.077 106.934,116.967 88.646,116.967 88.646,108.077
+5 on Bottom Layer "+5_L04_P027" (solid, pour order 27): 54.33,66.735 ccw(c97.701,66.735) 97.701,23.364 ccw(c97.701,66.735) 141.073,66.735 ccw(c97.701,66.735) 97.701,110.106 ccw(c97.701,66.735)

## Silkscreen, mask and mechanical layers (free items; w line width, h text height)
Top Overlay:
  text "_" at 105.821,106.649 h5 r335
  text "+" at 87.831,102.809 h5 r25
  text "_" at 70.744,98.858 h5 r25
  text "+" at 118.833,97.011 h5 r335
  text "SWD" at 116.432,61.187 h1.52
  text "GPIO" at 103.986,44.223 h1.52 r270
  text "NRST" at 98.779,44.096 h1.52 r270
  text "BOOT0" at 101.446,40.54 h1.52 r270
Mechanical 1:
  lines w0.254: 97.79,66.802 cw(c97.79,66.675) 97.917,66.675 ; 97.917,66.802 cw(c97.917,66.675) 98.044,66.675 ; 87.844,109.608 ccw(c97.874,66.722) 107.963,109.594 ccw(c107.963,109.606) 107.975,109.606 107.975,120.65 102.941,120.65 92.874,120.65 87.884,120.65 87.844,120.61 87.844,109.608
